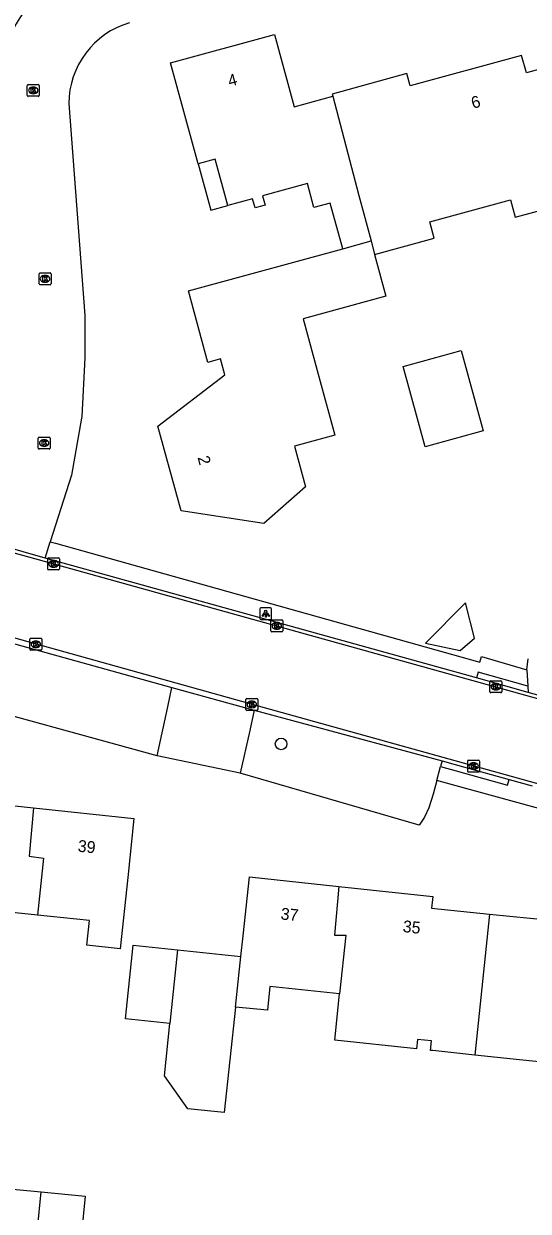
# Model space of a CAD drawing. Extents: x 162157 to 163165, y 378998 to 380775.
# Drawn here: x 162526.7 to 162569.3, y 380579.8 to 380679.9 of the extents above; entities that cross this region are included whole.
import ezdxf

# ---------------------------------------------------------------- set-up
doc = ezdxf.new("R2010")
doc.units = 0
for name, color, linetype in [('IMGEO_Berm_groen', 7, 'Continuous'), ('IMGEO_Boom', 7, 'Continuous'), ('IMGEO_Groenvoorziening', 7, 'Continuous'), ('IMGEO_Kolk', 7, 'Continuous'), ('IMGEO_Lichtpunt', 7, 'Continuous'), ('IMGEO_Pand', 7, 'Continuous'), ('IMGEO_Pand_nummerreeks', 7, 'Continuous'), ('IMGEO_Pand_overbouw', 7, 'Continuous'), ('IMGEO_Rijbaan_lokaal_gesloten', 7, 'Continuous'), ('IMGEO_Rijbaan_lokaal_open', 7, 'Continuous'), ('IMGEO_Voetpad_open', 7, 'Continuous')]:
    doc.layers.add(name, color=color, linetype=linetype)

msp = doc.modelspace()

# ---------------------------------------------------------------- linework, layer by layer
at = {"layer": 'IMGEO_Berm_groen'}
msp.add_lwpolyline([(162569.17, 380625.42), (162569.3, 380626.35)], dxfattribs=at)
at = {"layer": 'IMGEO_Boom'}
msp.add_circle((162548.45, 380619.17), 0.489, dxfattribs=at)
at = {"layer": 'IMGEO_Groenvoorziening'}
for points in [[(162537.98, 380618.18), (162519.77, 380623.16)], [(162561.59, 380616.08), (162561.28, 380614.93), (162560.91, 380613.78), (162560.55, 380612.98), (162560.11, 380612.31), (162545, 380616.71)]]:
    msp.add_lwpolyline(points, dxfattribs=at)
at = {"layer": 'IMGEO_Kolk'}
for p, q in [((162527.04, 380673.87), (162527.04, 380674.72)), ((162527.11, 380674.8), (162527.97, 380674.8)), ((162527.55, 380674.02), (162527.52, 380674.02)), ((162527.53, 380674.58), (162527.55, 380674.58)), ((162528.04, 380674.72), (162528.04, 380673.87)), ((162527.97, 380673.8), (162527.11, 380673.8)), ((162528.11, 380658.9), (162528.96, 380658.9)), ((162528.04, 380657.97), (162528.04, 380658.83)), ((162528.96, 380657.9), (162528.11, 380657.9)), ((162528.52, 380658.68), (162528.55, 380658.68)), ((162528.55, 380658.12), (162528.52, 380658.12)), ((162529.04, 380658.83), (162529.04, 380657.97)), ((162527.96, 380644.12), (162527.96, 380644.97)), ((162528.04, 380645.05), (162528.89, 380645.05)), ((162528.45, 380644.83), (162528.48, 380644.83)), ((162528.96, 380644.97), (162528.96, 380644.12)), ((162528.89, 380644.05), (162528.04, 380644.05)), ((162528.47, 380644.27), (162528.45, 380644.27)), ((162528.83, 380634.87), (162529.68, 380634.87)), ((162528.76, 380633.94), (162528.76, 380634.79)), ((162529.68, 380633.86), (162528.83, 380633.86)), ((162529.27, 380634.09), (162529.24, 380634.09)), ((162529.25, 380634.64), (162529.27, 380634.64)), ((162529.76, 380634.79), (162529.76, 380633.94)), ((162547.59, 380628.7), (162547.59, 380629.56)), ((162547.66, 380629.63), (162548.51, 380629.63)), ((162548.1, 380628.85), (162548.07, 380628.85)), ((162548.08, 380629.41), (162548.1, 380629.41)), ((162548.59, 380629.56), (162548.59, 380628.7)), ((162527.26, 380627.15), (162527.26, 380628.01)), ((162527.34, 380628.08), (162528.19, 380628.08)), ((162527.75, 380627.86), (162527.78, 380627.86)), ((162528.26, 380628.01), (162528.26, 380627.15)), ((162548.51, 380628.63), (162547.66, 380628.63)), ((162528.19, 380627.08), (162527.34, 380627.08)), ((162527.77, 380627.3), (162527.75, 380627.3)), ((162566.06, 380623.57), (162566.06, 380624.42)), ((162566.14, 380624.5), (162566.99, 380624.5)), ((162566.55, 380624.28), (162566.57, 380624.28)), ((162567.06, 380624.42), (162567.06, 380623.57)), ((162545.48, 380622.08), (162545.48, 380622.93)), ((162545.55, 380623), (162546.4, 380623)), ((162546.48, 380622.93), (162546.48, 380622.08)), ((162566.99, 380623.5), (162566.14, 380623.5)), ((162566.57, 380623.72), (162566.55, 380623.72)), ((162546.4, 380622), (162545.55, 380622)), ((162545.99, 380622.22), (162545.96, 380622.22)), ((162545.97, 380622.78), (162545.99, 380622.78)), ((162564.26, 380617.8), (162565.12, 380617.8)), ((162564.19, 380616.88), (162564.19, 380617.73)), ((162565.12, 380616.8), (162564.26, 380616.8)), ((162564.7, 380617.02), (162564.67, 380617.02)), ((162564.68, 380617.58), (162564.7, 380617.58)), ((162565.19, 380617.73), (162565.19, 380616.88))]:
    msp.add_line(p, q, dxfattribs=at)
for points in [[(162527.04, 380673.87), (162527.04, 380674.72)], [(162527.11, 380674.8), (162527.97, 380674.8)], [(162527.36, 380674.5), (162527.48, 380674.5), (162527.48, 380674.35), (162527.61, 380674.5), (162527.78, 380674.5), (162527.63, 380674.35), (162527.78, 380674.1), (162527.63, 380674.1), (162527.55, 380674.26), (162527.48, 380674.19), (162527.48, 380674.1), (162527.36, 380674.1), (162527.36, 380674.5)], [(162528.04, 380674.72), (162528.04, 380673.87)], [(162527.97, 380673.8), (162527.11, 380673.8)], [(162528.11, 380658.9), (162528.96, 380658.9)], [(162528.04, 380657.97), (162528.04, 380658.83)], [(162528.96, 380657.9), (162528.11, 380657.9)], [(162528.36, 380658.6), (162528.48, 380658.6), (162528.48, 380658.45), (162528.61, 380658.6), (162528.77, 380658.6), (162528.63, 380658.45), (162528.78, 380658.2), (162528.63, 380658.2), (162528.54, 380658.36), (162528.48, 380658.3), (162528.48, 380658.2), (162528.36, 380658.2), (162528.36, 380658.6)], [(162529.04, 380658.83), (162529.04, 380657.97)], [(162527.96, 380644.12), (162527.96, 380644.97)], [(162528.04, 380645.05), (162528.89, 380645.05)], [(162528.96, 380644.97), (162528.96, 380644.12)], [(162528.89, 380644.05), (162528.04, 380644.05)], [(162528.28, 380644.75), (162528.41, 380644.75), (162528.41, 380644.6), (162528.54, 380644.75), (162528.7, 380644.75), (162528.55, 380644.6), (162528.71, 380644.35), (162528.55, 380644.35), (162528.47, 380644.51), (162528.41, 380644.44), (162528.41, 380644.35), (162528.28, 380644.35), (162528.28, 380644.75)], [(162528.83, 380634.87), (162529.68, 380634.87)], [(162528.76, 380633.94), (162528.76, 380634.79)], [(162529.68, 380633.86), (162528.83, 380633.86)], [(162529.08, 380634.56), (162529.2, 380634.56), (162529.2, 380634.41), (162529.33, 380634.56), (162529.5, 380634.56), (162529.35, 380634.41), (162529.5, 380634.16), (162529.35, 380634.16), (162529.27, 380634.33), (162529.2, 380634.26), (162529.2, 380634.16), (162529.08, 380634.16), (162529.08, 380634.56)], [(162529.76, 380634.79), (162529.76, 380633.94)], [(162547.59, 380628.7), (162547.59, 380629.56)], [(162547.66, 380629.63), (162548.51, 380629.63)], [(162547.91, 380629.33), (162548.03, 380629.33), (162548.03, 380629.18), (162548.16, 380629.33), (162548.33, 380629.33), (162548.18, 380629.18), (162548.33, 380628.93), (162548.18, 380628.93), (162548.1, 380629.1), (162548.03, 380629.03), (162548.03, 380628.93), (162547.91, 380628.93), (162547.91, 380629.33)], [(162548.59, 380629.56), (162548.59, 380628.7)], [(162527.26, 380627.15), (162527.26, 380628.01)], [(162527.34, 380628.08), (162528.19, 380628.08)], [(162528.26, 380628.01), (162528.26, 380627.15)], [(162548.51, 380628.63), (162547.66, 380628.63)], [(162528.19, 380627.08), (162527.34, 380627.08)], [(162527.58, 380627.78), (162527.71, 380627.78), (162527.71, 380627.63), (162527.84, 380627.78), (162528, 380627.78), (162527.86, 380627.63), (162528.01, 380627.38), (162527.86, 380627.38), (162527.77, 380627.54), (162527.71, 380627.48), (162527.71, 380627.38), (162527.58, 380627.38), (162527.58, 380627.78)], [(162566.06, 380623.57), (162566.06, 380624.42)], [(162566.14, 380624.5), (162566.99, 380624.5)], [(162566.38, 380624.2), (162566.51, 380624.2), (162566.51, 380624.05), (162566.63, 380624.2), (162566.8, 380624.2), (162566.65, 380624.05), (162566.81, 380623.8), (162566.65, 380623.8), (162566.57, 380623.96), (162566.51, 380623.89), (162566.51, 380623.8), (162566.38, 380623.8), (162566.38, 380624.2)], [(162567.06, 380624.42), (162567.06, 380623.57)], [(162545.48, 380622.08), (162545.48, 380622.93)], [(162545.55, 380623), (162546.4, 380623)], [(162546.48, 380622.93), (162546.48, 380622.08)], [(162566.99, 380623.5), (162566.14, 380623.5)], [(162546.4, 380622), (162545.55, 380622)], [(162545.8, 380622.7), (162545.92, 380622.7), (162545.92, 380622.55), (162546.05, 380622.7), (162546.22, 380622.7), (162546.07, 380622.55), (162546.22, 380622.3), (162546.07, 380622.3), (162545.99, 380622.47), (162545.92, 380622.4), (162545.92, 380622.3), (162545.8, 380622.3), (162545.8, 380622.7)], [(162564.26, 380617.8), (162565.12, 380617.8)], [(162564.19, 380616.88), (162564.19, 380617.73)], [(162565.12, 380616.8), (162564.26, 380616.8)], [(162564.51, 380617.5), (162564.63, 380617.5), (162564.63, 380617.35), (162564.76, 380617.5), (162564.93, 380617.5), (162564.78, 380617.35), (162564.93, 380617.1), (162564.78, 380617.1), (162564.7, 380617.27), (162564.63, 380617.2), (162564.63, 380617.1), (162564.51, 380617.1), (162564.51, 380617.5)], [(162565.19, 380617.73), (162565.19, 380616.88)]]:
    msp.add_lwpolyline(points, dxfattribs=at)
for centre, start, end in [((162527.12, 380674.72), 91.552, 178.448), ((162527.12, 380674.72), 91.552, 178.448), ((162527.96, 380674.72), 1.552, 88.448), ((162527.96, 380674.72), 1.552, 88.448), ((162527.12, 380673.87), 181.552, 268.448), ((162527.12, 380673.87), 181.552, 268.448), ((162527.96, 380673.87), 271.552, 358.448), ((162527.96, 380673.87), 271.552, 358.448), ((162528.11, 380658.82), 91.552, 178.448), ((162528.11, 380658.82), 91.552, 178.448), ((162528.96, 380658.82), 1.552, 88.448), ((162528.96, 380658.82), 1.552, 88.448), ((162528.11, 380657.98), 181.552, 268.448), ((162528.11, 380657.98), 181.552, 268.448), ((162528.96, 380657.98), 271.552, 358.448), ((162528.96, 380657.98), 271.552, 358.448), ((162528.04, 380644.97), 91.552, 178.448), ((162528.04, 380644.97), 91.552, 178.448), ((162528.89, 380644.97), 1.552, 88.448), ((162528.89, 380644.97), 1.552, 88.448), ((162528.04, 380644.12), 181.552, 268.448), ((162528.04, 380644.12), 181.552, 268.448), ((162528.89, 380644.12), 271.552, 358.448), ((162528.89, 380644.12), 271.552, 358.448), ((162528.83, 380634.79), 91.552, 178.448), ((162528.83, 380634.79), 91.552, 178.448), ((162529.68, 380634.79), 1.552, 88.448), ((162529.68, 380634.79), 1.552, 88.448), ((162528.83, 380633.94), 181.552, 268.448), ((162528.83, 380633.94), 181.552, 268.448), ((162529.68, 380633.94), 271.552, 358.448), ((162529.68, 380633.94), 271.552, 358.448), ((162547.66, 380629.56), 91.552, 178.448), ((162547.66, 380629.56), 91.552, 178.448), ((162548.51, 380629.56), 1.552, 88.448), ((162548.51, 380629.56), 1.552, 88.448), ((162527.34, 380628), 91.552, 178.448), ((162527.34, 380628), 91.552, 178.448), ((162528.19, 380628), 1.552, 88.448), ((162528.19, 380628), 1.552, 88.448), ((162547.66, 380628.71), 181.552, 268.448), ((162547.66, 380628.71), 181.552, 268.448), ((162548.51, 380628.71), 271.552, 358.448), ((162548.51, 380628.71), 271.552, 358.448), ((162527.34, 380627.16), 181.552, 268.448), ((162527.34, 380627.16), 181.552, 268.448), ((162528.19, 380627.16), 271.552, 358.448), ((162528.19, 380627.16), 271.552, 358.448), ((162566.14, 380624.42), 91.552, 178.448), ((162566.14, 380624.42), 91.552, 178.448), ((162566.99, 380624.42), 1.552, 88.448), ((162566.99, 380624.42), 1.552, 88.448), ((162545.55, 380622.93), 91.552, 178.448), ((162545.55, 380622.93), 91.552, 178.448), ((162546.4, 380622.93), 1.552, 88.448), ((162546.4, 380622.93), 1.552, 88.448), ((162566.14, 380623.57), 181.552, 268.448), ((162566.14, 380623.57), 181.552, 268.448), ((162566.99, 380623.57), 271.552, 358.448), ((162566.99, 380623.57), 271.552, 358.448), ((162545.55, 380622.08), 181.552, 268.448), ((162545.55, 380622.08), 181.552, 268.448), ((162546.4, 380622.08), 271.552, 358.448), ((162546.4, 380622.08), 271.552, 358.448), ((162564.26, 380617.73), 91.552, 178.448), ((162564.26, 380617.73), 91.552, 178.448), ((162565.11, 380617.73), 1.552, 88.448), ((162565.11, 380617.73), 1.552, 88.448), ((162564.26, 380616.88), 181.552, 268.448), ((162564.26, 380616.88), 181.552, 268.448), ((162565.11, 380616.88), 271.552, 358.448), ((162565.11, 380616.88), 271.552, 358.448)]:
    msp.add_arc(centre, 0.0765, start, end, dxfattribs=at)
for centre, major_axis, ratio, start_param, end_param in [((162527.53, 380674.3), (-0.387, 0.002), 0.722429, 4.712389, 7.853982), ((162527.55, 380674.3), (-0.39, 0.002), 0.717154, 1.570796, 4.712389), ((162528.52, 380658.4), (-0.387, 0.002), 0.722429, 4.712389, 7.853982), ((162528.55, 380658.4), (-0.39, 0.002), 0.717154, 1.570796, 4.712389), ((162528.45, 380644.55), (-0.387, 0.002), 0.722429, 4.712389, 7.853982), ((162528.47, 380644.55), (-0.39, 0.002), 0.717154, 1.570796, 4.712389), ((162529.24, 380634.36), (-0.387, 0.002), 0.722429, 4.712389, 7.853982), ((162529.27, 380634.36), (-0.39, 0.002), 0.717154, 1.570796, 4.712389), ((162548.07, 380629.13), (-0.387, 0.002), 0.722429, 4.712389, 7.853982), ((162548.1, 380629.13), (-0.39, 0.002), 0.717154, 1.570796, 4.712389), ((162527.75, 380627.58), (-0.387, 0.002), 0.722429, 4.712389, 7.853982), ((162527.77, 380627.58), (-0.39, 0.002), 0.717154, 1.570796, 4.712389), ((162566.55, 380624), (-0.387, 0.002), 0.722429, 4.712389, 7.853982), ((162566.57, 380624), (-0.39, 0.002), 0.717154, 1.570796, 4.712389), ((162545.96, 380622.5), (-0.387, 0.002), 0.722429, 4.712389, 7.853982), ((162545.99, 380622.5), (-0.39, 0.002), 0.717154, 1.570796, 4.712389), ((162564.68, 380617.3), (-0.387, 0.002), 0.722429, 4.712389, 7.853982), ((162564.7, 380617.3), (-0.39, 0.002), 0.717154, 1.570796, 4.712389)]:
    msp.add_ellipse(centre, major_axis=major_axis, ratio=ratio, start_param=start_param, end_param=end_param, dxfattribs=at)
at = {"layer": 'IMGEO_Lichtpunt'}
for p, q in [((162546.65, 380630.56), (162546.65, 380629.75)), ((162546.65, 380630.56), (162546.65, 380629.75)), ((162547.55, 380630.65), (162546.75, 380630.65)), ((162547.55, 380630.65), (162546.75, 380630.65)), ((162547.65, 380629.75), (162547.65, 380630.56)), ((162547.65, 380629.75), (162547.65, 380630.56)), ((162546.75, 380629.66), (162547.55, 380629.66)), ((162546.75, 380629.66), (162547.55, 380629.66))]:
    msp.add_line(p, q, dxfattribs=at)
for points in [[(162547.03, 380630.22), (162547.06, 380630.19), (162546.88, 380629.93), (162546.84, 380629.96), (162547.03, 380630.22)], [(162547.13, 380630.17), (162547.18, 380630.17), (162547.18, 380629.85), (162547.13, 380629.85), (162547.13, 380630.17)], [(162547.24, 380630.19), (162547.28, 380630.22), (162547.46, 380629.96), (162547.42, 380629.93), (162547.24, 380630.19)]]:
    msp.add_lwpolyline(points, dxfattribs=at)
msp.add_circle((162547.15, 380630.36), 0.0994, dxfattribs=at)
for centre, start, end in [((162546.75, 380630.56), 90, 180), ((162546.75, 380630.56), 90, 180), ((162547.55, 380630.56), 0, 90), ((162547.55, 380630.56), 0, 90), ((162546.75, 380629.75), 180, 270), ((162546.75, 380629.75), 180, 270), ((162547.55, 380629.75), 270, 0), ((162547.55, 380629.75), 270, 360)]:
    msp.add_arc(centre, 0.0946, start, end, dxfattribs=at)
at = {"layer": 'IMGEO_Pand'}
for points in [[(162553.65, 380660.94), (162552.6, 380664.78), (162551.22, 380664.41), (162550.67, 380666.43), (162546.88, 380665.4), (162547.1, 380664.61), (162546.27, 380664.39), (162546.05, 380665.16), (162543.95, 380664.59), (162542.89, 380668.5), (162541.45, 380668.11), (162539.13, 380676.63), (162547.89, 380679.02), (162549.55, 380672.92), (162552.81, 380673.81)], [(162556.34, 380660.46), (162561.37, 380661.83), (162560.99, 380663.21), (162567.79, 380665.07), (162568.19, 380663.59), (162571.36, 380664.46), (162576.19, 380665.77), (162573.16, 380676.87), (162569.15, 380675.77), (162568.74, 380677.25), (162559.35, 380674.69), (162559.07, 380675.73), (162552.77, 380673.99), (162552.81, 380673.81)], [(162552.81, 380673.81), (162555, 380665.44), (162556.05, 380661.6)], [(162556.34, 380660.46), (162557.28, 380656.93), (162550.31, 380655.03), (162551.67, 380650.04), (162552.99, 380645.22), (162549.59, 380644.29), (162550.52, 380640.85), (162547, 380637.75), (162540.01, 380638.82), (162538.05, 380645.98), (162543.71, 380650.31), (162543.35, 380651.64), (162542.27, 380651.35), (162540.63, 380657.39), (162553.65, 380660.94)], [(162553.65, 380660.94), (162556.05, 380661.6)], [(162556.05, 380661.6), (162556.34, 380660.46)], [(162565.49, 380645.57), (162560.61, 380644.24), (162558.76, 380651.02), (162563.64, 380652.35), (162565.49, 380645.57)], [(162564, 380631.08), (162560.62, 380627.67), (162563.56, 380627.05), (162564.77, 380628.08), (162564, 380631.08)], [(162527.91, 380604.73), (162522.29, 380605.33), (162522.07, 380603.29), (162519.31, 380603.58), (162519.95, 380609.56), (162520.48, 380614.53), (162527.57, 380613.78)], [(162527.57, 380613.78), (162527.2, 380609.7), (162528.4, 380609.54), (162527.91, 380604.73)], [(162527.57, 380613.78), (162536.03, 380612.88), (162535.51, 380607.91), (162534.87, 380601.9), (162532.06, 380602.2), (162532.28, 380604.27), (162527.91, 380604.73)], [(162545.06, 380601.24), (162545.24, 380602.97), (162545.77, 380607.95), (162553.32, 380607.15)], [(162553.32, 380607.15), (162552.95, 380603.05), (162553.91, 380603.04), (162553.39, 380598.1)], [(162553.32, 380607.15), (162561.25, 380606.31), (162561.15, 380605.31), (162566.04, 380604.82)], [(162566.04, 380604.82), (162564.8, 380592.93)], [(162566.04, 380604.82), (162572.89, 380604.13), (162572.99, 380605.12), (162580.47, 380604.33)], [(162539.07, 380595.59), (162535.31, 380595.99), (162535.97, 380602.21), (162539.72, 380601.81)], [(162539.72, 380601.81), (162539.07, 380595.59)], [(162539.72, 380601.81), (162545.06, 380601.24)], [(162544.61, 380596.98), (162545.06, 380601.24)], [(162553.39, 380598.1), (162547.51, 380598.72), (162547.29, 380596.7), (162544.61, 380596.98)], [(162564.8, 380592.93), (162561.26, 380593.3), (162561.06, 380593.32), (162561.14, 380594.12), (162559.97, 380594.24), (162559.88, 380593.45), (162552.98, 380594.18), (162553.39, 380598.1)], [(162544.61, 380596.98), (162543.66, 380588.07), (162540.58, 380588.4), (162538.6, 380591.17), (162539.07, 380595.59)], [(162580.55, 380595.27), (162574.7, 380595.89), (162574.49, 380593.89), (162571.53, 380594.2), (162571.32, 380592.23), (162568.55, 380592.53), (162564.8, 380592.93)], [(162524.58, 380581.74), (162528.21, 380581.39)], [(162528.21, 380581.39), (162531.91, 380581.03), (162531.29, 380574.74), (162527.59, 380575.1)], [(162527.59, 380575.1), (162528.21, 380581.39)]]:
    msp.add_lwpolyline(points, dxfattribs=at)
at = {"layer": 'IMGEO_Pand_overbouw'}
msp.add_lwpolyline([(162541.45, 380668.11), (162542.52, 380664.2), (162543.95, 380664.59), (162542.89, 380668.5)], close=True, dxfattribs=at)
at = {"layer": 'IMGEO_Rijbaan_lokaal_gesloten'}
for points in [[(162495.12, 380643.82), (162500, 380642.47), (162522.29, 380636.3), (162522.65, 380636.2), (162528.46, 380634.59), (162577.26, 380621.02), (162615.79, 380610.25)], [(162600.25, 380607.43), (162547.05, 380622.21), (162522.04, 380629.18), (162520.44, 380629.62), (162500, 380635.26), (162493.4, 380637.09)], [(162520.47, 380629.14), (162539.24, 380623.93)], [(162539.24, 380623.93), (162546.18, 380622.01)], [(162546.18, 380622.01), (162562.03, 380617.74)], [(162562.03, 380617.74), (162563.33, 380617.39), (162567.7, 380616.17)], [(162567.7, 380616.17), (162569.64, 380615.63)]]:
    msp.add_lwpolyline(points, dxfattribs=at)
at = {"layer": 'IMGEO_Rijbaan_lokaal_open'}
for points in [[(162530.53, 380673.19), (162531.88, 380655.32), (162531.88, 380654.78), (162531.89, 380651.74), (162531.64, 380646.78), (162531.62, 380646.66), (162530.77, 380641.83), (162528.98, 380636.21)], [(162528.54, 380634.85), (162522.75, 380636.51)], [(162528.54, 380634.85), (162528.98, 380636.21)], [(162564.94, 380624.74), (162528.54, 380634.85)], [(162569.3, 380623.52), (162564.94, 380624.74)], [(162621.17, 380608.94), (162618.04, 380609.98), (162569.3, 380623.52)]]:
    msp.add_lwpolyline(points, dxfattribs=at)
for centre, radius, start, end in [((162536.84, 380673.75), 12.38, 103.6964, 178.1912), ((162537.71, 380673.12), 7.18, 106.5654, 179.4852)]:
    msp.add_arc(centre, radius, start, end, dxfattribs=at)
at = {"layer": 'IMGEO_Voetpad_open'}
for points in [[(162528.98, 380636.21), (162529.43, 380636.1), (162565.22, 380626.08), (162565.37, 380626.55), (162569.17, 380625.42)], [(162569.26, 380624.05), (162565.07, 380625.22), (162564.94, 380624.74)], [(162569.17, 380625.42), (162569.26, 380624.05)], [(162537.98, 380618.18), (162538.88, 380622.3), (162539.24, 380623.93)], [(162569.26, 380624.05), (162569.3, 380623.52)], [(162546.18, 380622.01), (162545.8, 380620.29), (162545, 380616.71)], [(162545, 380616.71), (162537.98, 380618.18)], [(162561.59, 380616.08), (162561.91, 380617.26)], [(162562.03, 380617.74), (162561.91, 380617.26)], [(162561.91, 380617.26), (162563.21, 380616.91), (162567.56, 380615.69), (162567.7, 380616.17)], [(162613.01, 380601.73), (162588.76, 380608.64), (162562.91, 380615.72), (162561.59, 380616.08)]]:
    msp.add_lwpolyline(points, dxfattribs=at)

# ---------------------------------------------------------------- texts
at = {"layer": 'IMGEO_Pand_nummerreeks'}
for s, rotation, p in [('4', 15.2579, (162544.11, 380674.59)), ('6', 15.2579, (162564.64, 380672.74)), ('2', 285.2519, (162541.39, 380643.33)), ('39', 353.9498, (162531.26, 380610.09)), ('37', 353.9496, (162548.38, 380604.37)), ('35', 353.9496, (162558.68, 380603.31))]:
    msp.add_text(s, height=1, rotation=rotation, dxfattribs=at).set_placement(p)

doc.saveas('drawing.dxf')
